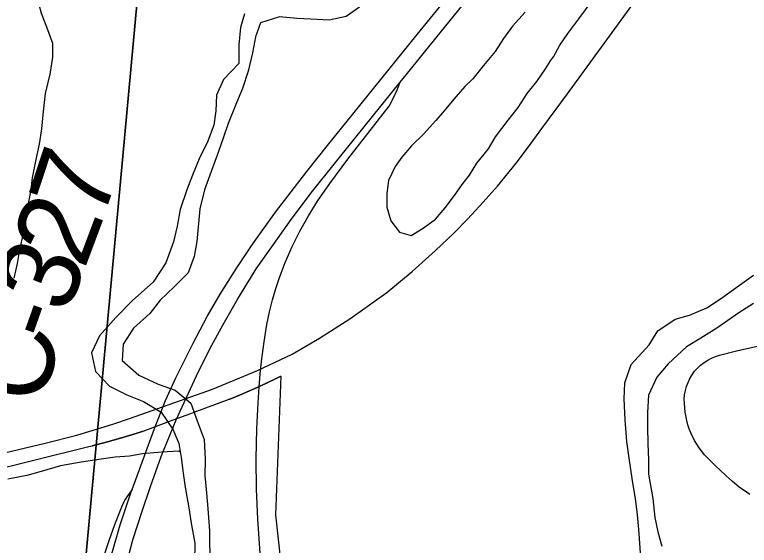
# Model space of a CAD drawing. Extents: x 0 to 34, y 0 to 22.
# Drawn here: x 7.128 to 7.657, y 18.219 to 18.601 of the extents above; entities that cross this region are included whole.
import ezdxf

# ---------------------------------------------------------------- set-up
doc = ezdxf.new("R2010")
doc.units = 0
for name, color, linetype in [('GM_X_City_Street', 7, 'Continuous'), ('GM_X_County_Road_Text', 7, 'Continuous'), ('GM_X_Interchange_Ramps', 7, 'Continuous'), ('GM_X_Major_River', 7, 'Continuous'), ('GM_X_Minor_Lake', 7, 'Continuous'), ('GM_X_Minor_River', 7, 'Continuous'), ('GM_X_Rail_Line', 7, 'Continuous'), ('GM_X_Section', 7, 'Continuous'), ('GM_X_US_Route', 7, 'Continuous'), ('SC_Shading1', 7, 'Continuous')]:
    doc.layers.add(name, color=color, linetype=linetype)

msp = doc.modelspace()

# ---------------------------------------------------------------- linework, layer by layer
at = {"layer": 'GM_X_City_Street'}
msp.add_lwpolyline([(7.65707, 18.25516), (7.6546, 18.25688), (7.64934, 18.26057), (7.64467, 18.26458), (7.64222, 18.26661), (7.64002, 18.26873), (7.63552, 18.27301), (7.63322, 18.27513), (7.62866, 18.27937), (7.62441, 18.28385), (7.62065, 18.28875), (7.61733, 18.29398), (7.61455, 18.29953), (7.61342, 18.30243), (7.61246, 18.30539), (7.61168, 18.3084), (7.61054, 18.31453), (7.61003, 18.32076), (7.60992, 18.32387), (7.61016, 18.32697), (7.61074, 18.33004), (7.61158, 18.33305), (7.61266, 18.33597), (7.61398, 18.33879), (7.61554, 18.34146), (7.61736, 18.34396), (7.61941, 18.34628), (7.62167, 18.34839), (7.62412, 18.35028), (7.62674, 18.35193), (7.6295, 18.35335), (7.63239, 18.35451), (7.63537, 18.35545), (7.64745, 18.35856), (7.66565, 18.36263)], dxfattribs=at)
at = {"layer": 'GM_X_Interchange_Ramps'}
for points in [[(7.30456, 18.21264), (7.30274, 18.23741), (7.30175, 18.25911), (7.30146, 18.28084), (7.30194, 18.30256), (7.303, 18.32116), (7.30377, 18.33285), (7.30478, 18.34471), (7.30564, 18.35284), (7.30734, 18.36521), (7.30927, 18.37754), (7.31116, 18.3867), (7.31324, 18.39541), (7.31571, 18.40347), (7.31813, 18.41064), (7.32254, 18.42231), (7.3275, 18.43375), (7.33304, 18.44493), (7.33917, 18.45579), (7.34582, 18.46634), (7.35465, 18.4792), (7.3677, 18.49671), (7.38866, 18.52379), (7.39731, 18.53495), (7.40045, 18.54094), (7.403, 18.54663), (7.40533, 18.55219)], [(7.21224, 18.25882), (7.20844, 18.25347), (7.20733, 18.25171), (7.20587, 18.24902), (7.20398, 18.24484), (7.1996, 18.23345), (7.19553, 18.22177), (7.19204, 18.2118)]]:
    msp.add_lwpolyline(points, dxfattribs=at)
at = {"layer": 'GM_X_Major_River'}
for points in [[(7.37595, 18.60613), (7.3663, 18.59952), (7.35409, 18.59677), (7.34082, 18.59746), (7.33097, 18.59807), (7.31847, 18.59913), (7.30471, 18.59489), (7.30105, 18.58471), (7.29888, 18.57336), (7.2959, 18.56013), (7.29181, 18.54768), (7.28738, 18.53714), (7.28133, 18.52246), (7.27806, 18.51265), (7.27439, 18.5021), (7.26912, 18.48778), (7.26424, 18.47459), (7.26088, 18.46099), (7.2588, 18.43747), (7.25701, 18.42649), (7.25256, 18.41482), (7.24245, 18.40479), (7.23235, 18.39515), (7.22491, 18.38544), (7.21327, 18.37508), (7.20578, 18.36347), (7.20512, 18.35171), (7.21702, 18.34117), (7.23091, 18.33476), (7.24332, 18.33029), (7.25449, 18.3209), (7.25912, 18.30825), (7.26411, 18.29484), (7.26491, 18.28076), (7.26463, 18.26899), (7.26552, 18.25871), (7.2664, 18.24804), (7.26731, 18.23852), (7.26785, 18.22901), (7.268, 18.21951), (7.26848, 18.20772)], [(7.29309, 18.60124), (7.2902, 18.59143), (7.28914, 18.57891), (7.2892, 18.56561), (7.27792, 18.55409), (7.27309, 18.5428), (7.27244, 18.53141), (7.27105, 18.52118), (7.26619, 18.50837), (7.26101, 18.49823), (7.25576, 18.48505), (7.25172, 18.47451), (7.24683, 18.46056), (7.24464, 18.44845), (7.24209, 18.43711), (7.23641, 18.42204), (7.22735, 18.40819), (7.21261, 18.39485), (7.20055, 18.3826), (7.18885, 18.36957), (7.18286, 18.35717)], [(7.57831, 18.21297), (7.57751, 18.22705), (7.57632, 18.24076), (7.57469, 18.2522), (7.57239, 18.26669), (7.57042, 18.27965), (7.56847, 18.29338), (7.56733, 18.30899), (7.56655, 18.32421), (7.5672, 18.33559), (7.5717, 18.34879), (7.58456, 18.36292), (7.59087, 18.37304), (7.60322, 18.38149), (7.61354, 18.38428), (7.62619, 18.38968), (7.63661, 18.39666), (7.64973, 18.40585), (7.65978, 18.41322)], [(7.65966, 18.3927), (7.64926, 18.3861), (7.63343, 18.37507), (7.62187, 18.36775), (7.61147, 18.36153), (7.59828, 18.3493), (7.59007, 18.33961), (7.58407, 18.32683), (7.5834, 18.31431), (7.58352, 18.30367), (7.58362, 18.29188), (7.58409, 18.28009), (7.58423, 18.26983), (7.58722, 18.25228), (7.58879, 18.23857), (7.59082, 18.22826), (7.59361, 18.21793)], [(7.18286, 18.35717), (7.18596, 18.3438), (7.19595, 18.3333), (7.20832, 18.32693), (7.22035, 18.32209), (7.23308, 18.31457), (7.24188, 18.30182), (7.24582, 18.29185), (7.24748, 18.28193), (7.2491, 18.27049), (7.25038, 18.26058), (7.25306, 18.2457), (7.2547, 18.23464), (7.25739, 18.22014), (7.25707, 18.20685)]]:
    msp.add_lwpolyline(points, dxfattribs=at)
at = {"layer": 'GM_X_Minor_Lake'}
for points in [[(7.51357, 18.56743), (7.51559, 18.5705), (7.5202, 18.57881), (7.52594, 18.58712), (7.53397, 18.59769), (7.54773, 18.61657)], [(7.49542, 18.60253), (7.48626, 18.59235), (7.47976, 18.58367), (7.47363, 18.57422), (7.46523, 18.56404), (7.45759, 18.5546), (7.45187, 18.54895), (7.44386, 18.5399), (7.43698, 18.5316), (7.43087, 18.52443), (7.4221, 18.51463), (7.41333, 18.50634), (7.40646, 18.49804), (7.40165, 18.49145)], [(7.40165, 18.49145), (7.39687, 18.48141), (7.39566, 18.47193), (7.39558, 18.46206), (7.39853, 18.45217), (7.4049, 18.44416), (7.41321, 18.44182), (7.42195, 18.44707), (7.4307, 18.45346), (7.43757, 18.46176), (7.44445, 18.47043), (7.44981, 18.47837), (7.45516, 18.48516), (7.46052, 18.49385), (7.46892, 18.50404), (7.47391, 18.51273), (7.48308, 18.52481), (7.49034, 18.53386), (7.49685, 18.54407), (7.50373, 18.55274), (7.50985, 18.56181), (7.51357, 18.56743)]]:
    msp.add_lwpolyline(points, dxfattribs=at)
at = {"layer": 'GM_X_Minor_River'}
for points in [[(7.12735, 18.41089), (7.1297, 18.4215), (7.13129, 18.43174), (7.13403, 18.44311), (7.13721, 18.46244), (7.13918, 18.47305), (7.1404, 18.48329), (7.14315, 18.49656), (7.1455, 18.50755), (7.1471, 18.51854), (7.14834, 18.53106), (7.14995, 18.54396), (7.15309, 18.55798), (7.15507, 18.57011), (7.15515, 18.57998), (7.1507, 18.59178), (7.147, 18.60168), (7.14369, 18.61423), (7.13242, 18.62456), (7.12611, 18.63979)], [(7.24686, 18.28563), (7.24592, 18.2863), (7.23343, 18.28564), (7.2198, 18.2846), (7.21033, 18.28277), (7.20011, 18.28208), (7.18989, 18.28064), (7.1755, 18.27847), (7.16072, 18.27592), (7.14669, 18.27185), (7.13646, 18.26889), (7.12282, 18.26633)]]:
    msp.add_lwpolyline(points, dxfattribs=at)
at = {"layer": 'GM_X_Rail_Line'}
msp.add_lwpolyline([(7.1109, 18.28295), (7.14949, 18.29222), (7.17232, 18.29805), (7.19823, 18.3058), (7.21097, 18.31025), (7.27005, 18.33117), (7.30244, 18.34451), (7.32739, 18.35617), (7.34728, 18.36789), (7.36904, 18.38159), (7.39566, 18.40077), (7.41393, 18.41573), (7.43076, 18.431), (7.44386, 18.44344), (7.45384, 18.4536), (7.46514, 18.46568), (7.47536, 18.47728), (7.48894, 18.49416), (7.4997, 18.50811), (7.50739, 18.51887), (7.52572, 18.54381), (7.63902, 18.69965), (7.66796, 18.73984)], dxfattribs=at)
at = {"layer": 'GM_X_Section'}
for points in [[(6.2677, 19.26674), (7.26758, 19.17046), (7.17505, 18.16824), (6.17707, 18.26412)], [(7.26758, 19.17046), (8.27199, 19.07297), (8.18593, 18.07293), (7.17505, 18.16824)]]:
    msp.add_lwpolyline(points, close=True, dxfattribs=at)
at = {"layer": 'GM_X_US_Route'}
for points in [[(7.29101, 18.42349), (7.29923, 18.43579), (7.31539, 18.45853), (7.33802, 18.4877), (7.35301, 18.5066), (7.38627, 18.54779), (7.41763, 18.58658), (7.4432, 18.6182), (7.46474, 18.64478), (7.49245, 18.67891), (7.53528, 18.73169), (7.56425, 18.76761)], [(7.30007, 18.4152), (7.30159, 18.4177), (7.31402, 18.43525), (7.32685, 18.45321), (7.34224, 18.47373), (7.37242, 18.51141), (7.40533, 18.55219), (7.40951, 18.55738), (7.43516, 18.58894), (7.4685, 18.63017), (7.50736, 18.67812), (7.56189, 18.74547), (7.57565, 18.76243)], [(7.21224, 18.25882), (7.22823, 18.30274), (7.23625, 18.3229), (7.24374, 18.33913), (7.25617, 18.36413), (7.26637, 18.38328), (7.27567, 18.39937), (7.28718, 18.41775), (7.29101, 18.42349)], [(7.24399, 18.30904), (7.25848, 18.34056), (7.26823, 18.36006), (7.27772, 18.37765), (7.28838, 18.396), (7.30007, 18.4152)], [(7.1856, 18.03469), (7.18562, 18.03577), (7.18588, 18.0505), (7.18596, 18.05219), (7.18655, 18.06502), (7.18703, 18.07533), (7.18822, 18.08956), (7.19049, 18.11204), (7.19338, 18.13399), (7.19661, 18.15202), (7.20077, 18.17408), (7.20713, 18.20135), (7.21268, 18.22249), (7.21937, 18.24329), (7.22538, 18.26108), (7.23324, 18.28258), (7.24399, 18.30904)], [(7.19761, 18.21236), (7.20353, 18.23333), (7.21164, 18.25716), (7.21224, 18.25882)]]:
    msp.add_lwpolyline(points, dxfattribs=at)
at = {"layer": 'SC_Shading1'}
msp.add_lwpolyline([(7.0668, 18.26134), (7.18096, 18.28969), (7.18347, 18.29031), (7.18364, 18.29036), (7.18382, 18.2904), (7.18399, 18.29045), (7.18417, 18.29049), (7.18435, 18.29054), (7.18452, 18.29058), (7.1847, 18.29063), (7.18487, 18.29067), (7.18505, 18.29072), (7.18522, 18.29076), (7.1854, 18.29081), (7.18557, 18.29085), (7.18575, 18.2909), (7.18593, 18.29094), (7.1861, 18.29099), (7.18628, 18.29104), (7.18645, 18.29108), (7.18663, 18.29113), (7.1868, 18.29117), (7.18698, 18.29122), (7.18715, 18.29126), (7.18733, 18.29131), (7.1875, 18.29136), (7.18768, 18.2914), (7.18786, 18.29145), (7.18803, 18.29149), (7.18821, 18.29154), (7.18838, 18.29159), (7.18856, 18.29163), (7.18873, 18.29168), (7.18891, 18.29173), (7.18908, 18.29177), (7.18926, 18.29182), (7.18943, 18.29187), (7.18961, 18.29191), (7.18978, 18.29196), (7.18996, 18.29201), (7.19013, 18.29205), (7.19031, 18.2921), (7.19048, 18.29215), (7.19066, 18.29219), (7.19083, 18.29224), (7.19101, 18.29229), (7.19119, 18.29233), (7.19136, 18.29238), (7.19154, 18.29243), (7.19171, 18.29248), (7.19189, 18.29252), (7.19206, 18.29257), (7.19224, 18.29262), (7.19241, 18.29266), (7.19259, 18.29271), (7.19276, 18.29276), (7.19294, 18.29281), (7.19311, 18.29285), (7.19346, 18.29295), (7.19364, 18.293), (7.19381, 18.29305), (7.19399, 18.29309), (7.19416, 18.29314), (7.19434, 18.29319), (7.19451, 18.29324), (7.19469, 18.29328), (7.19486, 18.29333), (7.19503, 18.29338), (7.19521, 18.29343), (7.19538, 18.29348), (7.19556, 18.29353), (7.19573, 18.29357), (7.19591, 18.29362), (7.19608, 18.29367), (7.19626, 18.29372), (7.19643, 18.29377), (7.19661, 18.29382), (7.19678, 18.29387), (7.19696, 18.29391), (7.19713, 18.29396), (7.19731, 18.29401), (7.19748, 18.29406), (7.19766, 18.29411), (7.198, 18.29421), (7.19818, 18.29426), (7.19835, 18.29431), (7.19853, 18.29435), (7.1987, 18.2944), (7.19888, 18.29445), (7.19905, 18.2945), (7.19923, 18.29455), (7.1994, 18.2946), (7.19958, 18.29465), (7.19975, 18.2947), (7.19992, 18.29475), (7.2001, 18.2948), (7.20027, 18.29485), (7.20045, 18.2949), (7.20062, 18.29495), (7.2008, 18.295), (7.20097, 18.29505), (7.20115, 18.2951), (7.20132, 18.29515), (7.20149, 18.2952), (7.20167, 18.29525), (7.20184, 18.2953), (7.20202, 18.29535), (7.20219, 18.2954), (7.20237, 18.29545), (7.20254, 18.2955), (7.20271, 18.29555), (7.20289, 18.2956), (7.20306, 18.29565), (7.20324, 18.2957), (7.20341, 18.29575), (7.20358, 18.2958), (7.20376, 18.29585), (7.20393, 18.2959), (7.20411, 18.29595), (7.20428, 18.296), (7.20445, 18.29606), (7.20463, 18.29611), (7.2048, 18.29616), (7.20498, 18.29621), (7.20515, 18.29626), (7.20533, 18.29631), (7.2055, 18.29636), (7.20567, 18.29641), (7.20585, 18.29646), (7.20602, 18.29652), (7.20619, 18.29657), (7.20637, 18.29662), (7.20654, 18.29667), (7.20672, 18.29672), (7.20689, 18.29677), (7.20706, 18.29682), (7.20724, 18.29688), (7.20741, 18.29693), (7.20759, 18.29698), (7.20776, 18.29703), (7.20793, 18.29708), (7.20805, 18.29712), (7.20811, 18.29714), (7.20828, 18.29719), (7.20845, 18.29724), (7.20863, 18.29729), (7.2088, 18.29734), (7.20898, 18.2974), (7.20915, 18.29745), (7.20932, 18.2975), (7.2095, 18.29755), (7.20967, 18.29761), (7.20984, 18.29766), (7.21002, 18.29771), (7.21019, 18.29776), (7.21036, 18.29782), (7.21071, 18.29792), (7.21088, 18.29797), (7.21106, 18.29803), (7.21123, 18.29808), (7.21141, 18.29813), (7.21158, 18.29818), (7.21175, 18.29824), (7.21193, 18.29829), (7.2121, 18.29834), (7.21227, 18.2984), (7.21245, 18.29845), (7.21262, 18.2985), (7.21279, 18.29856), (7.21297, 18.29861), (7.21314, 18.29866), (7.21331, 18.29872), (7.21349, 18.29877), (7.21366, 18.29882), (7.21383, 18.29888), (7.21401, 18.29893), (7.21418, 18.29898), (7.21435, 18.29904), (7.21452, 18.29909), (7.2147, 18.29915), (7.21487, 18.2992), (7.21504, 18.29925), (7.21522, 18.29931), (7.21539, 18.29936), (7.21556, 18.29942), (7.21574, 18.29947), (7.21608, 18.29958), (7.21626, 18.29963), (7.21643, 18.29969), (7.2166, 18.29974), (7.21678, 18.2998), (7.21695, 18.29985), (7.21712, 18.2999), (7.21729, 18.29996), (7.21747, 18.30001), (7.21764, 18.30007), (7.21781, 18.30012), (7.21799, 18.30018), (7.21816, 18.30023), (7.21833, 18.30029), (7.2185, 18.30034), (7.21868, 18.3004), (7.21885, 18.30045), (7.21902, 18.30051), (7.2192, 18.30056), (7.21937, 18.30062), (7.21954, 18.30067), (7.21971, 18.30073), (7.21989, 18.30078), (7.22006, 18.30084), (7.22023, 18.30089), (7.2419, 18.30891), (7.2545, 18.31357), (7.25696, 18.31448), (7.28217, 18.32381), (7.28234, 18.32388), (7.28251, 18.32395), (7.28268, 18.32402), (7.28285, 18.32409), (7.28302, 18.32416), (7.2832, 18.32423), (7.28337, 18.3243), (7.28354, 18.32436), (7.28371, 18.32443), (7.28388, 18.3245), (7.28405, 18.32457), (7.28422, 18.32464), (7.2844, 18.32471), (7.28457, 18.32478), (7.28474, 18.32485), (7.28491, 18.32492), (7.28508, 18.32499), (7.28525, 18.32506), (7.28542, 18.32513), (7.28559, 18.3252), (7.28576, 18.32527), (7.28594, 18.32534), (7.28611, 18.32541), (7.28628, 18.32548), (7.28645, 18.32555), (7.28662, 18.32562), (7.28679, 18.32569), (7.28696, 18.32576), (7.28713, 18.32583), (7.2873, 18.3259), (7.28747, 18.32597), (7.28765, 18.32605), (7.28782, 18.32612), (7.28799, 18.32619), (7.28816, 18.32626), (7.28833, 18.32633), (7.2885, 18.3264), (7.28867, 18.32647), (7.28884, 18.32654), (7.28901, 18.32661), (7.28918, 18.32668), (7.28935, 18.32676), (7.28952, 18.32683), (7.28969, 18.3269), (7.28986, 18.32697), (7.29003, 18.32704), (7.2902, 18.32711), (7.29038, 18.32719), (7.29055, 18.32726), (7.29072, 18.32733), (7.29089, 18.3274), (7.29106, 18.32747), (7.29123, 18.32754), (7.2914, 18.32762), (7.29157, 18.32769), (7.29174, 18.32776), (7.29191, 18.32783), (7.29208, 18.32791), (7.29225, 18.32798), (7.29242, 18.32805), (7.29259, 18.32812), (7.29276, 18.3282), (7.29293, 18.32827), (7.29327, 18.32841), (7.29344, 18.32849), (7.29361, 18.32856), (7.29378, 18.32863), (7.29395, 18.32871), (7.29412, 18.32878), (7.29429, 18.32885), (7.29446, 18.32892), (7.29463, 18.329), (7.29474, 18.32905), (7.2948, 18.32907), (7.29497, 18.32914), (7.29514, 18.32922), (7.29531, 18.32929), (7.29548, 18.32936), (7.29565, 18.32944), (7.29582, 18.32951), (7.29599, 18.32959), (7.29615, 18.32966), (7.29632, 18.32973), (7.29649, 18.32981), (7.29666, 18.32988), (7.29683, 18.32996), (7.297, 18.33003), (7.29717, 18.3301), (7.29734, 18.33018), (7.29751, 18.33025), (7.29768, 18.33033), (7.29785, 18.3304), (7.29802, 18.33048), (7.29819, 18.33055), (7.29836, 18.33062), (7.29853, 18.3307), (7.29869, 18.33077), (7.29886, 18.33085), (7.2992, 18.331), (7.29937, 18.33107), (7.29954, 18.33115), (7.29971, 18.33122), (7.29988, 18.3313), (7.30005, 18.33137), (7.30022, 18.33145), (7.30038, 18.33152), (7.30055, 18.3316), (7.30072, 18.33167), (7.30089, 18.33175), (7.30106, 18.33183), (7.30123, 18.3319), (7.3014, 18.33198), (7.30157, 18.33205), (7.30173, 18.33213), (7.3019, 18.3322), (7.30207, 18.33228), (7.30224, 18.33236), (7.30241, 18.33243), (7.30258, 18.33251), (7.30275, 18.33258), (7.30291, 18.33266), (7.30308, 18.33274), (7.30325, 18.33281), (7.30342, 18.33289), (7.30359, 18.33297), (7.30376, 18.33304), (7.30393, 18.33312), (7.30409, 18.3332), (7.30426, 18.33327), (7.30443, 18.33335), (7.3046, 18.33343), (7.30477, 18.3335), (7.30493, 18.33358), (7.3051, 18.33366), (7.30527, 18.33373), (7.30544, 18.33381), (7.30561, 18.33389), (7.30577, 18.33397), (7.30594, 18.33404), (7.30611, 18.33412), (7.30628, 18.3342), (7.30645, 18.33427), (7.30661, 18.33435), (7.30678, 18.33443), (7.30695, 18.33451), (7.30712, 18.33459), (7.30729, 18.33466), (7.30745, 18.33474), (7.30762, 18.33482), (7.30779, 18.3349), (7.30796, 18.33497), (7.30812, 18.33505), (7.30829, 18.33513), (7.30863, 18.33529), (7.30879, 18.33537), (7.30896, 18.33544), (7.30913, 18.33552), (7.3093, 18.3356), (7.30946, 18.33568), (7.30963, 18.33576), (7.3098, 18.33584), (7.30997, 18.33592), (7.31013, 18.33599), (7.3103, 18.33607), (7.31047, 18.33615), (7.31063, 18.33623), (7.3108, 18.33631), (7.31097, 18.33639), (7.31114, 18.33647), (7.3113, 18.33655), (7.31147, 18.33663), (7.31164, 18.33671), (7.3118, 18.33679), (7.31197, 18.33686), (7.31214, 18.33694), (7.31231, 18.33702), (7.31264, 18.33718), (7.31297, 18.33734), (7.31314, 18.33742), (7.31331, 18.3375), (7.31347, 18.33758), (7.31364, 18.33766), (7.31381, 18.33774), (7.31397, 18.33782), (7.31414, 18.3379), (7.31431, 18.33798), (7.31447, 18.33806), (7.31481, 18.33822), (7.31514, 18.33839), (7.3153, 18.33847), (7.31547, 18.33855), (7.31564, 18.33863), (7.31597, 18.33879), (7.31614, 18.33887), (7.3163, 18.33895), (7.31647, 18.33903), (7.31663, 18.33911), (7.3168, 18.33919), (7.31697, 18.33928), (7.31713, 18.33936), (7.3173, 18.33944), (7.31747, 18.33952), (7.31763, 18.3396), (7.3178, 18.33968), (7.31796, 18.33976), (7.31813, 18.33985), (7.31829, 18.33993), (7.31846, 18.34001), (7.31863, 18.34009), (7.31879, 18.34017), (7.31912, 18.34034), (7.31929, 18.34042), (7.31945, 18.3405), (7.3156, 18.24052), (7.32431, 18.15938)], dxfattribs=at)

# ---------------------------------------------------------------- texts
at = {"layer": 'GM_X_County_Road_Text'}
for s, rotation, p in [('7', 71.6066, (7.19069, 18.45132)), ('2', 69.483, (7.17775, 18.41663)), ('3', 69.2709, (7.16538, 18.38394)), ('-', 70.5259, (7.15779, 18.36245)), ('C', 80.6178, (7.1509, 18.31931))]:
    msp.add_text(s, height=0.05682, rotation=rotation, dxfattribs=at).set_placement(p)

doc.saveas('drawing.dxf')
